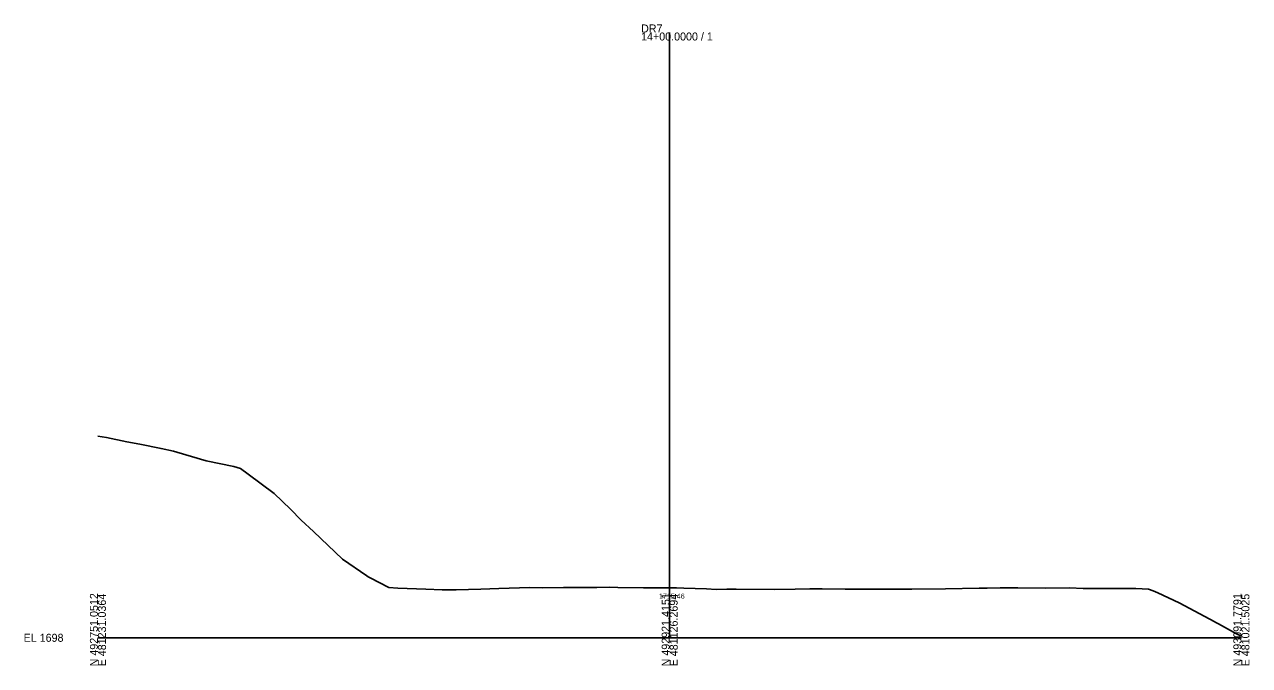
# Model space of a CAD drawing. Extents: x -26 to 403, y -10 to 4215.
# Drawn here: x -25.7 to 402.8, y 3990.3 to 4214.5 of the extents above; entities that cross this region are included whole.
import ezdxf

# ---------------------------------------------------------------- set-up
doc = ezdxf.new("R2010")
doc.units = 0
for name, color, linetype in [('Exist Cross Section Cell', 7, 'Continuous'), ('Exist XS Center Line Elevation Label', 7, 'Continuous'), ('Exist XS Ground Line', 7, 'Continuous')]:
    doc.layers.add(name, color=color, linetype=linetype)

msp = doc.modelspace()

# ---------------------------------------------------------------- linework, layer by layer
at = {"layer": 'Exist Cross Section Cell'}
for p, q in [((200, 4000), (200, 4211.73)), ((0, 4000), (200, 4000)), ((200, 4000), (400, 4000))]:
    msp.add_line(p, q, dxfattribs=at)
at = {"layer": 'Exist XS Ground Line'}
msp.add_lwpolyline([(0, 4070.58), (2.96, 4070.01), (10.07, 4068.58), (14.7, 4067.72), (22.09, 4066.18), (26.44, 4065.29), (27.55, 4064.94), (37.9, 4061.95), (47.54, 4059.96), (49.92, 4059.26), (52.58, 4057.24), (61.67, 4050.49), (67.36, 4045), (71.1, 4041.13), (75.37, 4037.2), (85.54, 4027.49), (94.11, 4021.64), (94.58, 4021.32), (95.25, 4020.97), (101.72, 4017.56), (104.88, 4017.33), (114.73, 4017.03), (120.38, 4016.82), (122, 4016.82), (125.28, 4016.81), (133.9, 4016.96), (140.25, 4017.26), (151.08, 4017.63), (155.6, 4017.48), (162.82, 4017.54), (167.34, 4017.6), (174.56, 4017.61), (179.08, 4017.65), (181.92, 4017.6), (190.83, 4017.48), (200, 4017.46), (201.01, 4017.46), (202.43, 4017.43), (204.9, 4017.35), (212.84, 4017.07), (216.27, 4016.93), (219.99, 4016.97), (223.32, 4016.95), (236.65, 4016.9), (243.96, 4017), (249.08, 4017.1), (253.35, 4017.12), (261.36, 4016.95), (265.15, 4017.04), (272.86, 4016.96), (274.68, 4017), (277.39, 4016.98), (284.76, 4016.98), (296.54, 4017.12), (308.25, 4017.4), (311.04, 4017.39), (315.57, 4017.47), (318.41, 4017.49), (321.81, 4017.47), (331.33, 4017.33), (339.82, 4017.45), (344.7, 4017.27), (351.11, 4017.28), (355.1, 4017.24), (360.45, 4017.23), (363.05, 4017.21), (367.49, 4017.06), (369.14, 4016.39), (370.8, 4015.67), (378.23, 4012.17), (383.74, 4009.3), (390.44, 4005.7), (391.01, 4005.35), (391.95, 4004.83), (398.28, 4001.34), (400, 4000.56)], dxfattribs=at)

# ---------------------------------------------------------------- texts
at = {"layer": 'Exist Cross Section Cell'}
for s, p in [('DR7', (190, 4211.73)), ('14+00.0000 / 1', (190, 4208.93)), ('EL 1698', (-26, 3998.6))]:
    msp.add_text(s, height=2.8, dxfattribs=at).set_placement(p)
for s, p in [('N 492751.0512', (0, 3990)), ('N 492921.4151', (200, 3990)), ('N 493091.7791', (400, 3990)), ('E 481231.0364', (2.8, 3990)), ('E 481126.2694', (202.8, 3990)), ('E 481021.5025', (402.8, 3990))]:
    msp.add_text(s, height=2.8, rotation=90, dxfattribs=at).set_placement(p)
at = {"layer": 'Exist XS Center Line Elevation Label'}
msp.add_text('1715.46', height=1.8, dxfattribs=at).set_placement((196.26, 4013.66))

doc.saveas('drawing.dxf')
